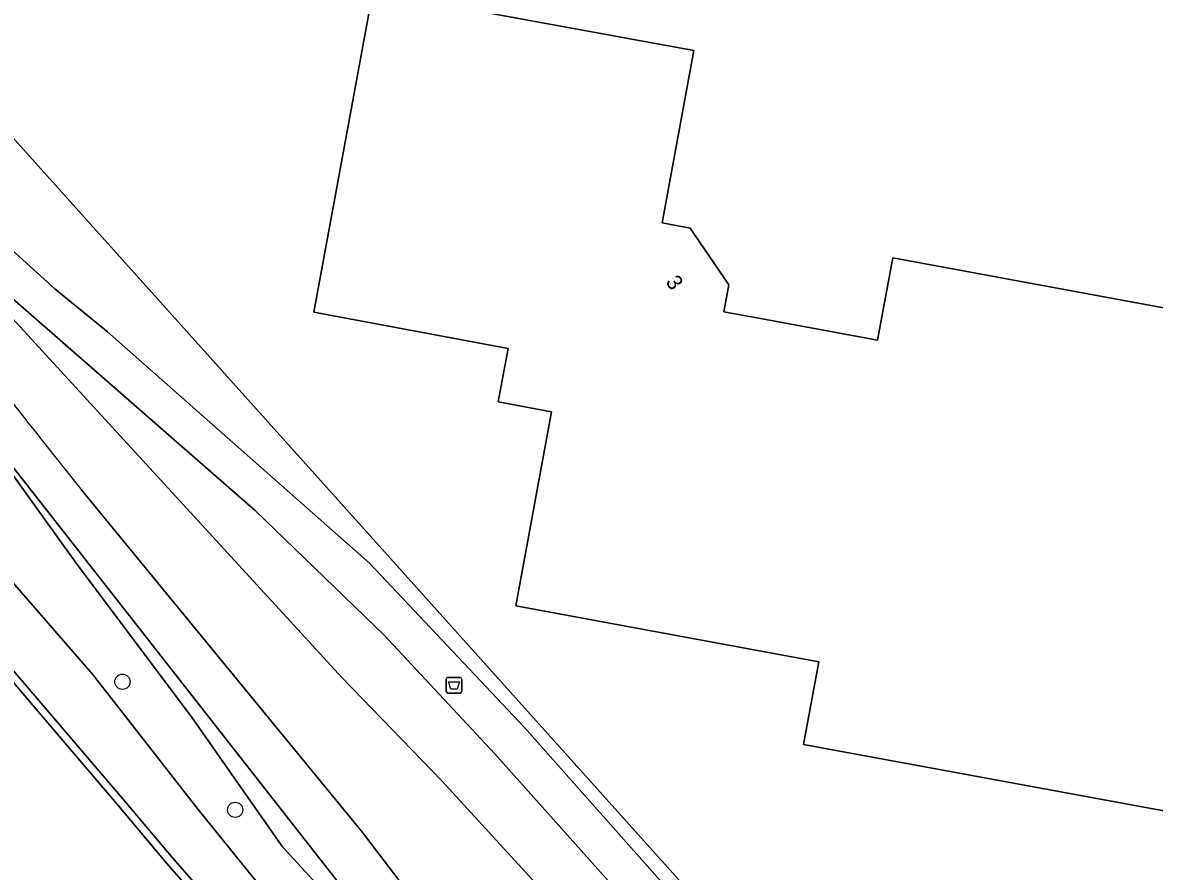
# Model space of a CAD drawing. Extents: x 157445 to 158888, y 383061 to 384688.
# Drawn here: x 157890.3 to 157963, y 383252.9 to 383307.4 of the extents above; entities that cross this region are included whole.
import ezdxf

# ---------------------------------------------------------------- set-up
doc = ezdxf.new("R2010")
doc.units = 0
for name, color, linetype in [('IMGEO_Afvalbak', 7, 'Continuous'), ('IMGEO_Boom', 7, 'Continuous'), ('IMGEO_Erf', 7, 'Continuous'), ('IMGEO_Groenvoorziening', 7, 'Continuous'), ('IMGEO_Hek', 7, 'Continuous'), ('IMGEO_Kademuur', 7, 'Continuous'), ('IMGEO_Pand', 7, 'Continuous'), ('IMGEO_Pand_nummerreeks', 7, 'Continuous'), ('IMGEO_Waterloop', 7, 'Continuous')]:
    doc.layers.add(name, color=color, linetype=linetype)

msp = doc.modelspace()

# ---------------------------------------------------------------- linework, layer by layer
at = {"layer": 'IMGEO_Afvalbak'}
for p, q in [((157917.52, 383264.424), (157917.52, 383265.224)), ((157917.52, 383265.224), (157917.52, 383264.424)), ((157917.62, 383265.324), (157918.41, 383265.324)), ((157918.41, 383265.324), (157917.62, 383265.324)), ((157918.51, 383265.224), (157918.51, 383264.424)), ((157918.51, 383264.424), (157918.51, 383265.224)), ((157918.41, 383264.324), (157917.62, 383264.324)), ((157917.62, 383264.324), (157918.41, 383264.324))]:
    msp.add_line(p, q, dxfattribs=at)
msp.add_lwpolyline([(157917.663, 383265.038), (157918.367, 383265.038), (157918.218, 383264.568), (157917.812, 383264.568), (157917.663, 383265.038)], dxfattribs=at)
for centre, start, end in [((157917.62, 383265.224), 90, 180), ((157917.62, 383265.224), 90, 180), ((157918.41, 383265.224), 0, 90), ((157918.41, 383265.224), 360, 90), ((157917.62, 383264.424), 180, 270), ((157917.62, 383264.424), 180, 270), ((157918.41, 383264.424), 270, 0), ((157918.41, 383264.424), 270, 0)]:
    msp.add_arc(centre, 0.1, start, end, dxfattribs=at)
at = {"layer": 'IMGEO_Boom'}
for centre in [(157896.704, 383265.049), (157903.951, 383256.816)]:
    msp.add_circle(centre, 0.489, dxfattribs=at)
at = {"layer": 'IMGEO_Erf'}
msp.add_lwpolyline([(157849.702, 383344.141), (157889.589, 383300.088), (157949.885, 383232.91), (157999.103, 383263.082), (158003.179, 383265.58), (157976.607, 383304.584), (157965.542, 383320.73)], dxfattribs=at)
msp.add_lwpolyline([(157973.956, 383287.176), (157968.185, 383255.919), (157940.482, 383261.02), (157941.47, 383266.327), (157921.996, 383269.931), (157924.28, 383282.398), (157920.851, 383283.039), (157921.496, 383286.457), (157909.007, 383288.798), (157912.788, 383309.42), (157933.424, 383305.609), (157931.787, 383296.632), (157931.406, 383294.544), (157933.186, 383294.192), (157935.682, 383290.562), (157935.356, 383288.832), (157937.476, 383288.439), (157945.227, 383287.003), (157946.228, 383292.288)], close=True, dxfattribs=at)
at = {"layer": 'IMGEO_Groenvoorziening'}
for points in [[(157922.54, 383262.113), (157933.282, 383250), (157948.97, 383232.31), (157949.885, 383232.91), (157889.589, 383300.088), (157849.702, 383344.141), (157807.532, 383390.715), (157805.588, 383392.998), (157803.74, 383395.36), (157793.514, 383406.385), (157792.453, 383406.432), (157792.436, 383405.693), (157792.897, 383398.29), (157821.749, 383365.653), (157839.418, 383345.491), (157844.559, 383339.577), (157857.156, 383325.085), (157878.365, 383302.971), (157892.353, 383290.294), (157895.75, 383287.54), (157912.574, 383272.677)], [(157943.413, 383231.061), (157945.627, 383232.424), (157929.936, 383250), (157920.644, 383260.408), (157913.495, 383268.061), (157905.243, 383276.051), (157904.085, 383277.064), (157883.671, 383294.861), (157910.822, 383265.299), (157917.229, 383258.691), (157925.187, 383250), (157939.437, 383233.814), (157942.331, 383230.946), (157943.249, 383231.859), (157943.819, 383231.467)]]:
    msp.add_lwpolyline(points, close=True, dxfattribs=at)
for points in [[(157819.868, 383363.95), (157840.702, 383340.129), (157856.871, 383321.74), (157876.952, 383300.826), (157877.178, 383300.624), (157883.671, 383294.861), (157904.085, 383277.064), (157905.243, 383276.051), (157913.495, 383268.061), (157920.644, 383260.408), (157929.936, 383250), (157945.627, 383232.424), (157943.413, 383231.061), (157948.97, 383232.31), (157933.282, 383250), (157922.54, 383262.113), (157912.574, 383272.677), (157895.75, 383287.54), (157892.353, 383290.294), (157878.365, 383302.971), (157857.156, 383325.085), (157844.559, 383339.577), (157839.418, 383345.491), (157821.749, 383365.653)], [(157880.943, 383294.572), (157879.22, 383297.075), (157877.178, 383300.624), (157876.952, 383300.826), (157856.871, 383321.74), (157866.539, 383308.593), (157869.685, 383304.315), (157885.528, 383284.108), (157912.27, 383250), (157922.645, 383237.116), (157934.23, 383222.168), (157951.825, 383203.476), (157953.334, 383204.497)], [(157854.953, 383312.545), (157859.97, 383307.251), (157866.336, 383300.067), (157877.055, 383287.129), (157879.083, 383284.208), (157881.179, 383281.998), (157884.324, 383277.835), (157888.045, 383273.242), (157894.788, 383265.544), (157901.575, 383256.835), (157908.535, 383248.235), (157917.651, 383237.226), (157926.842, 383225.106), (157922.86, 383234.47), (157918.267, 383241.049), (157915.529, 383245.154), (157906.995, 383254.443), (157901.188, 383262.739), (157893.63, 383272.831), (157887.593, 383281.168), (157885.528, 383284.108), (157869.685, 383304.315), (157866.539, 383308.593)], [(157937.017, 383227.429), (157942.096, 383230.712), (157942.331, 383230.946), (157939.437, 383233.814), (157925.187, 383250), (157917.229, 383258.691), (157910.822, 383265.299), (157883.671, 383294.861), (157877.178, 383300.624), (157879.22, 383297.075), (157880.943, 383294.572)], [(157912.27, 383250), (157885.528, 383284.108)], [(157887.593, 383281.168), (157893.63, 383272.831), (157901.188, 383262.739), (157906.995, 383254.443), (157915.529, 383245.154), (157918.267, 383241.049), (157922.86, 383234.47), (157926.842, 383225.106), (157917.651, 383237.226), (157908.535, 383248.235), (157901.575, 383256.835), (157894.788, 383265.544), (157888.045, 383273.242)], [(157894.055, 383277.412), (157912.075, 383255.444), (157916.222, 383250), (157935.965, 383225.269)], [(157935.965, 383225.269), (157916.222, 383250), (157912.075, 383255.444), (157894.055, 383277.412)], [(157887.821, 383267.935), (157896.835, 383257.389), (157899.945, 383253.705), (157912.362, 383239.528)]]:
    msp.add_lwpolyline(points, dxfattribs=at)
msp.add_arc((158195.03, 383520.977), 387.182, 215.78542, 218.98165, dxfattribs=at)
msp.add_arc((158195.03, 383520.977), 387.182, 215.78542, 218.98165, dxfattribs=at)
at = {"layer": 'IMGEO_Hek'}
msp.add_lwpolyline([(157949.885, 383232.91), (157889.589, 383300.088)], dxfattribs=at)
at = {"layer": 'IMGEO_Kademuur'}
msp.add_lwpolyline([(157833.403, 383330.862), (157838.382, 383325.044), (157853.494, 383307.318), (157866.203, 383292.293), (157876.661, 383280.152), (157887.441, 383267.609), (157896.454, 383257.066), (157899.566, 383253.379), (157914.743, 383236.05), (157915.119, 383236.379), (157914.241, 383237.382), (157912.362, 383239.528), (157899.945, 383253.705), (157896.835, 383257.389), (157887.821, 383267.935), (157877.04, 383280.478), (157866.583, 383292.617), (157853.875, 383307.642), (157838.763, 383325.368), (157833.781, 383331.188)], dxfattribs=at)
at = {"layer": 'IMGEO_Pand'}
msp.add_lwpolyline([(157937.476, 383288.439), (157935.356, 383288.832), (157935.682, 383290.562), (157933.186, 383294.192), (157931.406, 383294.544), (157931.787, 383296.632), (157933.424, 383305.609), (157912.788, 383309.42), (157909.007, 383288.798), (157921.496, 383286.457), (157920.851, 383283.039), (157924.28, 383282.398), (157921.996, 383269.931), (157941.47, 383266.327), (157940.482, 383261.02), (157968.185, 383255.919), (157973.956, 383287.176), (157946.228, 383292.288), (157945.227, 383287.003)], close=True, dxfattribs=at)
at = {"layer": 'IMGEO_Waterloop'}
msp.add_lwpolyline([(157946.4, 383199.807), (157944.601, 383201.856), (157943.617, 383202.977), (157941.395, 383205.507), (157940.166, 383206.907), (157935.826, 383211.851), (157933.777, 383214.184), (157929.724, 383218.801), (157929.65, 383218.885), (157929.467, 383219.093), (157928.353, 383220.362), (157928.485, 383220.483), (157920.661, 383229.179), (157917.579, 383232.684), (157917.955, 383233.014), (157918.506, 383232.387), (157919.157, 383233.059), (157914.909, 383237.909), (157914.241, 383237.382), (157915.119, 383236.379), (157914.743, 383236.05), (157899.566, 383253.379), (157896.454, 383257.066), (157887.441, 383267.609)], dxfattribs=at)

# ---------------------------------------------------------------- texts
at = {"layer": 'IMGEO_Pand_nummerreeks'}
msp.add_text('3', height=1, rotation=304.51254, dxfattribs=at).set_placement((157931.577, 383290.743))

doc.saveas('drawing.dxf')
